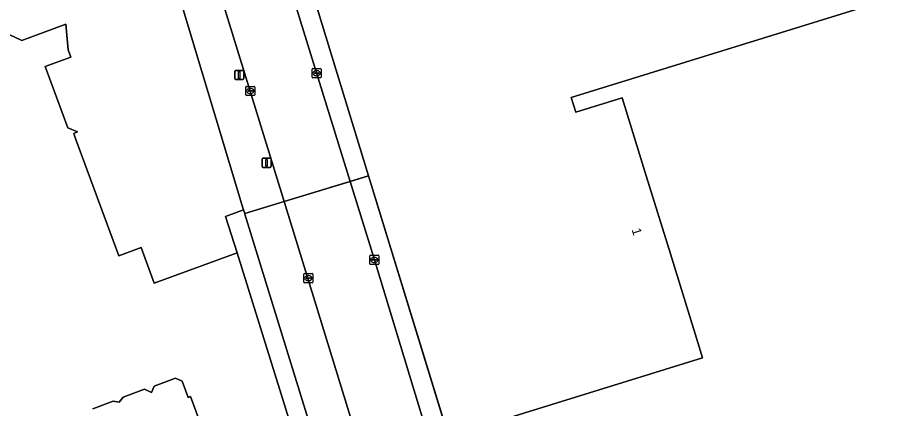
# Model space of a CAD drawing. Extents: x 160806 to 161707, y 383696 to 384148.
# Drawn here: x 161082.8 to 161177.4, y 383930 to 383972.9 of the extents above; entities that cross this region are included whole.
import ezdxf

# ---------------------------------------------------------------- set-up
doc = ezdxf.new("R2010")
doc.units = 0
for name, color, linetype in [('IMGEO_Erf', 7, 'Continuous'), ('IMGEO_Fietspad_gesloten', 7, 'Continuous'), ('IMGEO_Kolk', 7, 'Continuous'), ('IMGEO_Lichtmast', 7, 'Continuous'), ('IMGEO_Pand', 7, 'Continuous'), ('IMGEO_Pand_nummerreeks', 7, 'Continuous'), ('IMGEO_Pand_overbouw', 7, 'Continuous'), ('IMGEO_Terreindeel_gesloten', 7, 'Continuous'), ('IMGEO_Voetpad_open', 7, 'Continuous')]:
    doc.layers.add(name, color=color, linetype=linetype)

msp = doc.modelspace()

# ---------------------------------------------------------------- linework, layer by layer
at = {"layer": 'IMGEO_Erf'}
msp.add_lwpolyline([(161107.408, 384024.109), (161106.928, 384021.186), (161106.784, 384020.283), (161105.349, 384011.638), (161106.437, 384005.758), (161105.911, 384005.605), (161107.16, 384001.487), (161115.101, 383975.756), (161174.941, 383994.27), (161177.371, 383986.415), (161171.512, 383984.603), (161172.182, 383982.438), (161174.353, 383983.11), (161177.012, 383974.513), (161143.485, 383964.14), (161143.98, 383962.542), (161149.045, 383964.109), (161151.693, 383955.552), (161154.338, 383947.003), (161157.491, 383936.811), (161157.865, 383935.602), (161130.022, 383926.988)], dxfattribs=at)
at = {"layer": 'IMGEO_Fietspad_gesloten'}
msp.add_lwpolyline([(161096.658, 384002.717), (161097.481, 384000.05), (161112.041, 383952.737), (161119.258, 383954.945), (161104.758, 384001.93), (161103.731, 384005.273), (161103.627, 384007.38)], dxfattribs=at)
msp.add_lwpolyline([(161121.915, 383946.336), (161119.258, 383954.945), (161112.041, 383952.737), (161120.194, 383926.245), (161120.308, 383925.869), (161120.828, 383924.144), (161128.001, 383926.363)], close=True, dxfattribs=at)
at = {"layer": 'IMGEO_Kolk'}
for p, q in [((161115.093, 383966.38), (161115.093, 383967.232)), ((161115.168, 383967.306), (161116.02, 383967.306)), ((161115.352, 383966.8), (161115.352, 383966.812)), ((161115.79, 383966.763), (161115.392, 383966.763)), ((161115.395, 383966.849), (161115.793, 383966.849)), ((161115.604, 383966.526), (161115.579, 383966.526)), ((161115.581, 383967.086), (161115.606, 383967.086)), ((161115.836, 383966.812), (161115.836, 383966.8)), ((161116.094, 383967.232), (161116.094, 383966.38)), ((161116.02, 383966.306), (161115.168, 383966.306)), ((161107.828, 383964.435), (161107.828, 383965.287)), ((161107.903, 383965.361), (161108.755, 383965.361)), ((161108.087, 383964.855), (161108.087, 383964.867)), ((161108.525, 383964.818), (161108.127, 383964.818)), ((161108.13, 383964.904), (161108.528, 383964.904)), ((161108.339, 383964.581), (161108.314, 383964.581)), ((161108.316, 383965.141), (161108.341, 383965.141)), ((161108.571, 383964.867), (161108.571, 383964.855)), ((161108.829, 383965.287), (161108.829, 383964.435)), ((161108.755, 383964.361), (161107.903, 383964.361)), ((161121.414, 383945.91), (161121.414, 383946.762)), ((161121.489, 383946.836), (161122.341, 383946.836)), ((161121.902, 383946.616), (161121.927, 383946.616)), ((161122.415, 383946.762), (161122.415, 383945.91)), ((161122.341, 383945.836), (161121.489, 383945.836)), ((161121.673, 383946.33), (161121.673, 383946.342)), ((161122.111, 383946.293), (161121.713, 383946.293)), ((161121.716, 383946.379), (161122.114, 383946.379)), ((161121.925, 383946.056), (161121.9, 383946.056)), ((161122.157, 383946.342), (161122.157, 383946.33)), ((161114.183, 383943.904), (161114.183, 383944.756)), ((161114.258, 383944.83), (161115.11, 383944.83)), ((161115.184, 383944.756), (161115.184, 383943.904)), ((161115.11, 383943.83), (161114.258, 383943.83)), ((161114.442, 383944.324), (161114.442, 383944.336)), ((161114.88, 383944.287), (161114.482, 383944.287)), ((161114.485, 383944.373), (161114.883, 383944.373)), ((161114.694, 383944.05), (161114.669, 383944.05)), ((161114.671, 383944.61), (161114.696, 383944.61)), ((161114.926, 383944.336), (161114.926, 383944.324))]:
    msp.add_line(p, q, dxfattribs=at)
for points in [[(161115.093, 383966.38), (161115.093, 383967.232)], [(161115.168, 383967.306), (161116.02, 383967.306)], [(161116.094, 383967.232), (161116.094, 383966.38)], [(161116.02, 383966.306), (161115.168, 383966.306)], [(161107.828, 383964.435), (161107.828, 383965.287)], [(161107.903, 383965.361), (161108.755, 383965.361)], [(161108.829, 383965.287), (161108.829, 383964.435)], [(161108.755, 383964.361), (161107.903, 383964.361)], [(161121.414, 383945.91), (161121.414, 383946.762)], [(161121.489, 383946.836), (161122.341, 383946.836)], [(161122.415, 383946.762), (161122.415, 383945.91)], [(161122.341, 383945.836), (161121.489, 383945.836)], [(161114.183, 383943.904), (161114.183, 383944.756)], [(161114.258, 383944.83), (161115.11, 383944.83)], [(161115.184, 383944.756), (161115.184, 383943.904)], [(161115.11, 383943.83), (161114.258, 383943.83)]]:
    msp.add_lwpolyline(points, dxfattribs=at)
for centre, radius, start, end in [((161115.17, 383967.23), 0.0765, 91.55205, 178.44795), ((161115.17, 383967.23), 0.0765, 91.55205, 178.44795), ((161115.392, 383966.809), 0.0403, 85.87752, 175.75265), ((161115.389, 383966.799), 0.0366, 178.93798, 274.71019), ((161115.793, 383966.806), 0.043, 264.86636, 352.45326), ((161115.797, 383966.811), 0.0386, 1.73085, 96.63898), ((161116.018, 383967.23), 0.0765, 1.55205, 88.44795), ((161116.018, 383967.23), 0.0765, 1.55205, 88.44795), ((161115.17, 383966.382), 0.0765, 181.55205, 268.44795), ((161115.17, 383966.382), 0.0765, 181.55205, 268.44795), ((161116.018, 383966.382), 0.0765, 271.55205, 358.44795), ((161116.018, 383966.382), 0.0765, 271.55205, 358.44795), ((161107.905, 383965.285), 0.0765, 91.55205, 178.44795), ((161107.905, 383965.285), 0.0765, 91.55205, 178.44795), ((161108.127, 383964.864), 0.0403, 85.87752, 175.75265), ((161108.124, 383964.854), 0.0366, 178.93798, 274.71019), ((161108.528, 383964.861), 0.043, 264.86636, 352.45326), ((161108.532, 383964.866), 0.0386, 1.73085, 96.63898), ((161108.753, 383965.285), 0.0765, 1.55205, 88.44795), ((161108.753, 383965.285), 0.0765, 1.55205, 88.44795), ((161107.905, 383964.437), 0.0765, 181.55205, 268.44795), ((161107.905, 383964.437), 0.0765, 181.55205, 268.44795), ((161108.753, 383964.437), 0.0765, 271.55205, 358.44795), ((161108.753, 383964.437), 0.0765, 271.55205, 358.44795), ((161121.491, 383946.76), 0.0765, 91.55205, 178.44795), ((161121.491, 383946.76), 0.0765, 91.55205, 178.44795), ((161122.339, 383946.76), 0.0765, 1.55205, 88.44795), ((161122.339, 383946.76), 0.0765, 1.55205, 88.44795), ((161121.491, 383945.912), 0.0765, 181.55205, 268.44795), ((161121.491, 383945.912), 0.0765, 181.55205, 268.44795), ((161121.713, 383946.339), 0.0403, 85.87752, 175.75265), ((161121.71, 383946.329), 0.0366, 178.93798, 274.71019), ((161122.114, 383946.336), 0.043, 264.86636, 352.45326), ((161122.118, 383946.341), 0.0386, 1.73085, 96.63898), ((161122.339, 383945.912), 0.0765, 271.55205, 358.44795), ((161122.339, 383945.912), 0.0765, 271.55205, 358.44795), ((161114.26, 383944.754), 0.0765, 91.55205, 178.44795), ((161114.26, 383944.754), 0.0765, 91.55205, 178.44795), ((161115.108, 383944.754), 0.0765, 1.55205, 88.44795), ((161115.108, 383944.754), 0.0765, 1.55205, 88.44795), ((161114.26, 383943.906), 0.0765, 181.55205, 268.44795), ((161114.26, 383943.906), 0.0765, 181.55205, 268.44795), ((161114.482, 383944.333), 0.0403, 85.87752, 175.75265), ((161114.479, 383944.323), 0.0366, 178.93798, 274.71019), ((161114.883, 383944.33), 0.043, 264.86636, 352.45326), ((161114.887, 383944.335), 0.0386, 1.73085, 96.63898), ((161115.108, 383943.906), 0.0765, 271.55205, 358.44795), ((161115.108, 383943.906), 0.0765, 271.55205, 358.44795)]:
    msp.add_arc(centre, radius, start, end, dxfattribs=at)
for centre, major_axis, ratio, start_param, end_param in [((161115.58, 383966.806), (-0.387, 0.002), 0.722429, 4.712389, 7.853982), ((161115.605, 383966.806), (-0.39, 0.002), 0.717154, 1.570796, 4.712389), ((161108.315, 383964.861), (-0.387, 0.002), 0.722429, 4.712389, 7.853982), ((161108.34, 383964.861), (-0.39, 0.002), 0.717154, 1.570796, 4.712389), ((161121.901, 383946.336), (-0.387, 0.002), 0.722429, 4.712389, 7.853982), ((161121.926, 383946.336), (-0.39, 0.002), 0.717154, 1.570796, 4.712389), ((161114.67, 383944.33), (-0.387, 0.002), 0.722429, 4.712389, 7.853982), ((161114.695, 383944.33), (-0.39, 0.002), 0.717154, 1.570796, 4.712389)]:
    msp.add_ellipse(centre, major_axis=major_axis, ratio=ratio, start_param=start_param, end_param=end_param, dxfattribs=at)
at = {"layer": 'IMGEO_Lichtmast'}
for p, q in [((161106.621, 383966.209), (161106.621, 383967.009)), ((161106.621, 383967.009), (161106.621, 383966.209)), ((161106.721, 383967.109), (161107.511, 383967.109)), ((161107.511, 383967.109), (161106.721, 383967.109)), ((161107.611, 383967.009), (161107.611, 383966.209)), ((161107.611, 383966.209), (161107.611, 383967.009)), ((161107.511, 383966.109), (161106.721, 383966.109)), ((161106.721, 383966.109), (161107.511, 383966.109)), ((161109.619, 383956.578), (161109.619, 383957.378)), ((161109.619, 383957.378), (161109.619, 383956.578)), ((161109.719, 383957.478), (161110.509, 383957.478)), ((161110.509, 383957.478), (161109.719, 383957.478)), ((161110.609, 383957.378), (161110.609, 383956.578)), ((161110.609, 383956.578), (161110.609, 383957.378)), ((161110.509, 383956.478), (161109.719, 383956.478)), ((161109.719, 383956.478), (161110.509, 383956.478))]:
    msp.add_line(p, q, dxfattribs=at)
for points in [[(161107.041, 383966.984), (161107.191, 383966.984), (161107.191, 383966.234), (161107.041, 383966.234), (161107.041, 383966.984)], [(161110.039, 383957.353), (161110.189, 383957.353), (161110.189, 383956.603), (161110.039, 383956.603), (161110.039, 383957.353)]]:
    msp.add_lwpolyline(points, dxfattribs=at)
for centre, start, end in [((161106.721, 383967.009), 90, 180), ((161106.721, 383967.009), 90, 180), ((161107.511, 383967.009), 0, 90), ((161107.511, 383967.009), 360, 90), ((161106.721, 383966.209), 180, 270), ((161106.721, 383966.209), 180, 270), ((161107.511, 383966.209), 270, 0), ((161107.511, 383966.209), 270, 0), ((161109.719, 383957.378), 90, 180), ((161109.719, 383957.378), 90, 180), ((161110.509, 383957.378), 0, 90), ((161110.509, 383957.378), 360, 90), ((161109.719, 383956.578), 180, 270), ((161109.719, 383956.578), 180, 270), ((161110.509, 383956.578), 270, 0), ((161110.509, 383956.578), 270, 0)]:
    msp.add_arc(centre, 0.1, start, end, dxfattribs=at)
at = {"layer": 'IMGEO_Pand'}
for points in [[(161154.338, 383947.003), (161151.693, 383955.552), (161149.045, 383964.109), (161143.98, 383962.542), (161143.485, 383964.14), (161177.012, 383974.513), (161174.353, 383983.11), (161172.182, 383982.438), (161171.512, 383984.603), (161177.371, 383986.415), (161174.941, 383994.27), (161115.101, 383975.756), (161121.28, 383955.564), (161129.654, 383928.199), (161130.022, 383926.988), (161157.865, 383935.602), (161157.491, 383936.811)], [(161107.738, 383951.357), (161107.72, 383951.415), (161107.6, 383951.813), (161105.62, 383951.085), (161106.884, 383947.107), (161114.626, 383922.225), (161116.526, 383922.813), (161116.164, 383924.025)]]:
    msp.add_lwpolyline(points, close=True, dxfattribs=at)
for points in [[(161082.015, 383971.009), (161083.322, 383970.394), (161088.121, 383972.173), (161088.381, 383969.366), (161088.671, 383968.566), (161085.868, 383967.537), (161088.341, 383960.814), (161089.4, 383960.366), (161088.989, 383960.21), (161089.243, 383959.541), (161093.935, 383946.784), (161096.394, 383947.689), (161097.811, 383943.794), (161106.884, 383947.107), (161105.62, 383951.085), (161107.6, 383951.813), (161107.531, 383952.042), (161100.111, 383976.738)], [(161103.75, 383926.041), (161101.771, 383931.352), (161101.538, 383931.265), (161100.88, 383933.031), (161100.135, 383933.371), (161097.815, 383932.507), (161097.499, 383931.815), (161096.758, 383932.153), (161094.401, 383931.275), (161093.962, 383930.744), (161093.331, 383930.85), (161091.076, 383930.01)]]:
    msp.add_lwpolyline(points, dxfattribs=at)
at = {"layer": 'IMGEO_Pand_overbouw'}
msp.add_lwpolyline([(161121.28, 383955.564), (161107.72, 383951.415), (161107.738, 383951.357), (161116.164, 383924.025), (161116.526, 383922.813), (161130.022, 383926.988)], close=True, dxfattribs=at)
at = {"layer": 'IMGEO_Terreindeel_gesloten'}
for points in [[(161114.626, 383922.225), (161106.884, 383947.107), (161097.811, 383943.794), (161096.394, 383947.689), (161093.935, 383946.784), (161089.243, 383959.541), (161088.989, 383960.21), (161089.4, 383960.366), (161088.341, 383960.814), (161085.868, 383967.537), (161088.671, 383968.566), (161088.381, 383969.366), (161088.121, 383972.173), (161083.322, 383970.394), (161082.015, 383971.009)], [(161091.076, 383930.01), (161093.331, 383930.85), (161093.962, 383930.744), (161094.401, 383931.275), (161096.758, 383932.153), (161097.499, 383931.815), (161097.815, 383932.507), (161100.135, 383933.371), (161100.88, 383933.031), (161101.538, 383931.265), (161101.771, 383931.352), (161103.75, 383926.041)]]:
    msp.add_lwpolyline(points, dxfattribs=at)
at = {"layer": 'IMGEO_Voetpad_open'}
for points in [[(161097.884, 384019.582), (161099.091, 384024.316), (161087.151, 384018.873), (161098.143, 383982.971), (161099.73, 383978.043), (161100.111, 383976.738), (161107.531, 383952.042), (161107.6, 383951.813), (161107.72, 383951.415), (161112.041, 383952.737), (161097.481, 384000.05), (161096.658, 384002.717)], [(161103.627, 384007.38), (161103.731, 384005.273), (161104.758, 384001.93), (161119.258, 383954.945), (161121.28, 383955.564), (161115.101, 383975.756)]]:
    msp.add_lwpolyline(points, dxfattribs=at)
for points in [[(161121.28, 383955.564), (161119.258, 383954.945), (161121.915, 383946.336), (161128.001, 383926.363), (161130.022, 383926.988), (161129.654, 383928.199)], [(161112.041, 383952.737), (161107.72, 383951.415), (161107.738, 383951.357), (161116.164, 383924.025), (161116.526, 383922.813), (161120.828, 383924.144), (161120.308, 383925.869), (161120.194, 383926.245)]]:
    msp.add_lwpolyline(points, close=True, dxfattribs=at)

# ---------------------------------------------------------------- texts
at = {"layer": 'IMGEO_Pand_nummerreeks'}
msp.add_text('1', height=1, rotation=287.19206, dxfattribs=at).set_placement((161150.087, 383949.645))

doc.saveas('drawing.dxf')
